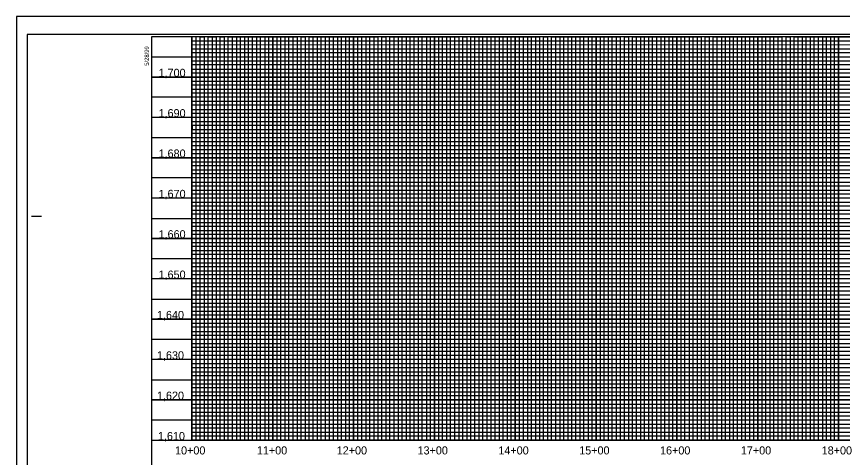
# Model space of a CAD drawing. Extents: x 497599 to 513368, y 404140 to 482942.
# Drawn here: x 505692 to 506714, y 439315 to 439861 of the extents above; entities that cross this region are included whole.
import ezdxf

# ---------------------------------------------------------------- set-up
doc = ezdxf.new("R2010")
doc.units = 0
for name, color, linetype in [('Exist Vertical Profile Vertical Axis Label', 7, 'Continuous'), ('Sheet Cutting Line CELL', 7, 'Continuous'), ('Sheet DOT Grid CELL', 7, 'Continuous'), ('Sheet Layout Profile Border Port 1', 7, 'Continuous'), ('Sheet Plot Border Inside CELL', 7, 'Continuous'), ('Sheet Plot Border Outside CELL', 7, 'Continuous'), ('Sheet Profile CELL', 7, 'Continuous'), ('Sheet Profile Grid Major CELL', 7, 'Continuous'), ('Sheet Profile Grid Middle CELL', 7, 'Continuous'), ('Sheet Profile Grid Minor CELL', 7, 'Continuous')]:
    doc.layers.add(name, color=color, linetype=linetype)

msp = doc.modelspace()

# ---------------------------------------------------------------- linework, layer by layer
at = {"layer": 'Sheet Cutting Line CELL'}
for p, q in [((507375.7, 439861.1), (505691.7, 439861.1)), ((505691.7, 439861.1), (505691.7, 438761.1))]:
    msp.add_line(p, q, dxfattribs=at)
at = {"layer": 'Sheet DOT Grid CELL'}
for p, q in [((505908.7, 439336.1), (505908.7, 439836.1)), ((505958.7, 439336.1), (505958.7, 439836.1)), ((506008.7, 439336.1), (506008.7, 439836.1)), ((506058.7, 439336.1), (506058.7, 439836.1)), ((506108.7, 439336.1), (506108.7, 439836.1)), ((506158.7, 439336.1), (506158.7, 439836.1)), ((506208.7, 439336.1), (506208.7, 439836.1)), ((506258.7, 439336.1), (506258.7, 439836.1)), ((506308.7, 439336.1), (506308.7, 439836.1)), ((506358.7, 439336.1), (506358.7, 439836.1)), ((506408.7, 439336.1), (506408.7, 439836.1)), ((506458.7, 439336.1), (506458.7, 439836.1)), ((506508.7, 439336.1), (506508.7, 439836.1)), ((506558.7, 439336.1), (506558.7, 439836.1)), ((506608.7, 439336.1), (506608.7, 439836.1)), ((506658.7, 439336.1), (506658.7, 439836.1)), ((506708.7, 439336.1), (506708.7, 439836.1)), ((507158.6, 439786.1), (505858.7, 439786.1)), ((507158.6, 439736.1), (505858.7, 439736.1)), ((507158.7, 439686.1), (505858.7, 439686.1)), ((507358.7, 439636.1), (505858.7, 439636.1)), ((507358.7, 439586.1), (505858.7, 439586.1)), ((507358.7, 439536.1), (505858.7, 439536.1)), ((507358.7, 439486.1), (505858.7, 439486.1)), ((507358.7, 439436.1), (505858.7, 439436.1)), ((507358.7, 439386.1), (505858.7, 439386.1))]:
    msp.add_line(p, q, dxfattribs=at)
at = {"layer": 'Sheet Layout Profile Border Port 1'}
msp.add_lwpolyline([(505908.7, 439831.1), (507158.7, 439831.1), (507158.6, 439675.1), (507308.7, 439675.1), (507308.7, 439336.1), (505908.7, 439336.1)], close=True, dxfattribs=at)
at = {"layer": 'Sheet Plot Border Inside CELL'}
msp.add_lwpolyline([(505704.7, 438783.6), (507371.2, 438783.6), (507371.2, 439838.7), (505704.7, 439838.7)], close=True, dxfattribs=at)
at = {"layer": 'Sheet Plot Border Outside CELL'}
msp.add_lwpolyline([(505691.7, 438761.1), (507375.7, 438761.1), (507375.7, 439861.1), (505691.7, 439861.1)], close=True, dxfattribs=at)
at = {"layer": 'Sheet Profile CELL'}
for p, q in [((505710.2, 439613.6), (505722.7, 439613.6)), ((505858.7, 439336.1), (507358.7, 439336.1))]:
    msp.add_line(p, q, dxfattribs=at)
msp.add_lwpolyline([(507358.7, 439836.1), (505858.7, 439836.1), (505858.7, 438786.1), (507358.7, 438786.1)], close=True, dxfattribs=at)
at = {"layer": 'Sheet Profile Grid Major CELL'}
for points in [[(505908.7, 439836.1), (505908.7, 439336.1), (505958.7, 439336.1), (505958.7, 439836.1), (506008.7, 439836.1), (506008.7, 439336.1), (506058.7, 439336.1), (506058.7, 439836.1), (506108.7, 439836.1), (506108.7, 439336.1), (506158.7, 439336.1), (506158.7, 439836.1), (506208.7, 439836.1), (506208.7, 439336.1), (506258.7, 439336.1), (506258.7, 439836.1), (506308.7, 439836.1), (506308.7, 439336.1), (506358.7, 439336.1), (506358.7, 439836.1), (506408.7, 439836.1), (506408.7, 439336.1), (506458.7, 439336.1), (506458.7, 439836.1), (506508.7, 439836.1), (506508.7, 439336.1), (506558.7, 439336.1), (506558.7, 439836.1), (506608.7, 439836.1), (506608.7, 439336.1), (506658.7, 439336.1), (506658.7, 439836.1), (506708.7, 439836.1), (506708.7, 439336.1), (506758.7, 439336.1)], [(505858.7, 439786.1), (507158.7, 439786.1)], [(507158.7, 439736.1), (505858.7, 439736.1), (505858.7, 439686.1), (507158.7, 439686.1)], [(507358.7, 439636.1), (505858.7, 439636.1), (505858.7, 439586.1), (507358.7, 439586.1)], [(507358.7, 439536.1), (505858.7, 439536.1), (505858.7, 439486.1), (507358.7, 439486.1)], [(507358.7, 439436.1), (505858.7, 439436.1), (505858.7, 439436.1), (505858.7, 439386.1), (507358.7, 439386.1)]]:
    msp.add_lwpolyline(points, dxfattribs=at)
at = {"layer": 'Sheet Profile Grid Middle CELL'}
msp.add_line((505858.7, 439811.1), (507158.6, 439811.1), dxfattribs=at)
for points in [[(505933.7, 439836.1), (505933.7, 439336.1), (505983.7, 439336.1), (505983.7, 439836.1), (506033.7, 439836.1), (506033.7, 439336.1), (506083.7, 439336.1), (506083.7, 439836.1), (506133.7, 439836.1), (506133.7, 439336.1), (506183.7, 439336.1), (506183.7, 439836.1), (506233.7, 439836.1), (506233.7, 439336.1), (506283.7, 439336.1), (506283.7, 439836.1), (506333.7, 439836.1), (506333.7, 439336.1), (506383.7, 439336.1), (506383.7, 439836.1), (506433.7, 439836.1), (506433.7, 439336.1), (506483.7, 439336.1), (506483.7, 439336.1), (506483.7, 439836.1), (506533.7, 439836.1), (506533.7, 439336.1), (506583.7, 439336.1), (506583.7, 439836.1), (506633.7, 439836.1), (506633.7, 439336.1), (506683.7, 439336.1), (506683.7, 439836.1), (506733.7, 439836.1)], [(507158.7, 439761.1), (505858.7, 439761.1), (505858.7, 439711.1), (507158.7, 439711.1)], [(507358.7, 439661.1), (505858.7, 439661.1), (505858.7, 439611.1), (507183.7, 439611.1)], [(507358.7, 439561.1), (505858.7, 439561.1), (505858.7, 439511.1), (507358.7, 439511.1)], [(507358.7, 439461.1), (505858.7, 439461.1), (505858.7, 439411.1), (507358.7, 439411.1)], [(507358.7, 439361.1), (505858.7, 439361.1)]]:
    msp.add_lwpolyline(points, dxfattribs=at)
at = {"layer": 'Sheet Profile Grid Minor CELL'}
for p, q in [((505908.7, 439831.1), (507158.7, 439831.1)), ((505908.7, 439826.1), (505908.7, 439826.1)), ((507158.7, 439826.1), (505908.7, 439825.8)), ((505908.7, 439821.1), (507158.7, 439821.1)), ((507158.6, 439701.1), (505908.7, 439701.1)), ((507158.7, 439696.1), (505908.7, 439696.1)), ((507158.7, 439691.1), (505908.7, 439691.1)), ((505908.7, 439681.1), (507158.7, 439681.1)), ((507158.7, 439676.1), (505908.7, 439676.1)), ((505908.7, 439671.1), (507308.7, 439671.1)), ((507308.7, 439651.1), (505908.7, 439651.1)), ((505908.7, 439646.1), (507308.7, 439646.1)), ((507308.7, 439626.1), (505908.7, 439626.1)), ((505908.7, 439621.1), (507308.7, 439621.1)), ((507308.7, 439601.1), (505908.7, 439601.1)), ((505908.7, 439596.1), (507308.7, 439596.1)), ((507308.7, 439591.1), (505908.7, 439591.1)), ((505908.7, 439581.1), (507308.7, 439581.1)), ((507308.7, 439576.1), (505908.7, 439576.1)), ((505908.7, 439571.1), (507308.7, 439571.1)), ((507308.7, 439566.1), (505908.7, 439566.1)), ((505908.7, 439556.1), (507308.7, 439556.1)), ((507308.7, 439551.1), (505908.7, 439551.1)), ((505908.7, 439546.1), (507308.7, 439546.1)), ((507308.7, 439541.1), (505908.7, 439541.1)), ((505908.7, 439531.1), (507308.7, 439531.1)), ((507308.7, 439526.1), (505908.7, 439526.1)), ((505908.7, 439521.1), (507308.7, 439521.1)), ((507308.7, 439516.1), (505908.7, 439516.1)), ((505908.7, 439506.1), (507308.7, 439506.1)), ((507308.7, 439501.1), (505908.7, 439501.1)), ((505908.7, 439496.1), (507308.7, 439496.1)), ((507308.7, 439491.1), (505908.7, 439491.1)), ((505908.7, 439481.1), (507308.7, 439481.1)), ((507308.7, 439476.1), (505908.7, 439476.1)), ((505908.7, 439471.1), (507308.7, 439471.1)), ((507308.7, 439466.1), (505908.7, 439466.1)), ((505908.7, 439456.1), (507308.7, 439456.1)), ((507308.7, 439451.1), (505908.7, 439451.1)), ((507308.7, 439446.1), (505908.7, 439446.1)), ((507308.7, 439441.1), (505908.7, 439441.1)), ((505908.7, 439431.1), (507308.7, 439431.1)), ((507308.7, 439426.1), (505908.7, 439426.1)), ((505908.7, 439421.1), (507308.7, 439421.1)), ((507308.7, 439416.1), (505908.7, 439416.1)), ((505908.7, 439406.1), (507308.7, 439406.1)), ((507308.7, 439401.1), (505908.7, 439401.1)), ((505908.7, 439396.1), (507308.7, 439396.1)), ((507308.7, 439391.1), (505908.7, 439391.1)), ((505908.7, 439381.1), (507308.7, 439381.1)), ((507308.7, 439376.1), (505908.7, 439376.1)), ((505908.7, 439371.1), (507308.7, 439371.1)), ((507308.7, 439366.1), (505908.7, 439366.1)), ((505908.7, 439356.1), (507308.7, 439356.1)), ((507308.7, 439351.1), (505908.7, 439351.1)), ((505908.7, 439346.1), (507308.7, 439346.1))]:
    msp.add_line(p, q, dxfattribs=at)
for points in [[(505913.7, 439836.1), (505913.7, 439336.1), (505918.7, 439336.1), (505918.7, 439836.1), (505923.7, 439836.1), (505923.7, 439336.1), (505928.7, 439336.1), (505928.7, 439836.1), (505938.7, 439836.1), (505938.7, 439336.1), (505943.7, 439336.1), (505943.7, 439836.1), (505948.7, 439836.1), (505948.7, 439336.1), (505953.7, 439336.1), (505963.7, 439336.1), (505968.7, 439336.1), (505968.7, 439836.1), (505973.7, 439836.1), (505973.7, 439336.1), (505978.7, 439336.1), (505978.7, 439836.1), (505988.7, 439836.1), (505988.7, 439336.1), (505993.7, 439336.1), (505993.7, 439836.1), (505998.7, 439836.1), (505998.7, 439336.1), (506003.7, 439336.1), (506003.7, 439836.1), (506013.7, 439836.1), (506013.7, 439336.1), (506018.7, 439336.1), (506018.7, 439836.1), (506023.7, 439836.1), (506023.7, 439336.1), (506028.7, 439336.1), (506028.7, 439836.1), (506038.7, 439836.1), (506038.7, 439336.1), (506043.7, 439336.1), (506043.7, 439836.1), (506048.7, 439836.1), (506048.7, 439336.1), (506053.7, 439336.1), (506053.7, 439836.1), (506063.7, 439836.1), (506063.7, 439336.1), (506068.7, 439336.1), (506068.7, 439836.1), (506073.7, 439836.1), (506073.7, 439336.1), (506078.7, 439336.1), (506078.7, 439836.1), (506088.7, 439836.1), (506088.7, 439336.1), (506093.7, 439336.1), (506093.7, 439836.1), (506098.7, 439836.1), (506098.7, 439336.1), (506103.7, 439336.1), (506103.7, 439836.1), (506113.7, 439836.1), (506113.7, 439336.1), (506118.7, 439336.1), (506118.7, 439836.1), (506123.7, 439836.1), (506123.7, 439336.1)], [(505953.7, 439336.1), (505953.7, 439836.1), (505963.7, 439836.1), (505963.7, 439336.1)], [(506123.7, 439336.1), (506128.7, 439336.1), (506128.7, 439836.1), (506138.7, 439836.1), (506138.7, 439336.1), (506143.7, 439336.1), (506143.7, 439836.1), (506148.7, 439836.1), (506148.7, 439336.1), (506153.7, 439336.1), (506153.7, 439836.1), (506163.7, 439836.1), (506163.7, 439336.1), (506168.7, 439336.1), (506168.7, 439836.1), (506173.7, 439836.1), (506173.7, 439336.1), (506178.7, 439336.1), (506178.7, 439836.1), (506188.7, 439836.1), (506188.7, 439336.1), (506193.7, 439336.1), (506193.7, 439836.1), (506198.7, 439836.1), (506198.7, 439336.1), (506203.7, 439336.1), (506203.7, 439836.1), (506213.7, 439836.1), (506213.7, 439336.1), (506218.7, 439336.1), (506218.7, 439836.1), (506223.7, 439836.1), (506223.7, 439336.1), (506228.7, 439336.1), (506228.7, 439836.1), (506238.7, 439836.1), (506238.7, 439336.1), (506243.7, 439336.1), (506243.7, 439836.1), (506248.7, 439836.1), (506248.7, 439336.1), (506253.7, 439336.1), (506253.7, 439836.1), (506263.7, 439836.1), (506263.7, 439336.1), (506268.7, 439336.1), (506268.7, 439836.1), (506273.7, 439836.1), (506273.7, 439336.1), (506278.7, 439336.1), (506278.7, 439836.1), (506288.7, 439836.1), (506288.7, 439336.1), (506293.7, 439336.1), (506293.7, 439836.1), (506298.7, 439836.1), (506298.7, 439336.1), (506303.7, 439336.1), (506303.7, 439836.1), (506313.7, 439836.1), (506313.7, 439336.1), (506318.7, 439336.1), (506318.7, 439836.1), (506323.7, 439836.1), (506323.7, 439336.1), (506328.7, 439336.1), (506328.7, 439836.1), (506338.7, 439836.1), (506338.7, 439336.1), (506343.7, 439336.1), (506343.7, 439836.1), (506348.7, 439836.1), (506348.7, 439336.1), (506353.7, 439336.1), (506353.7, 439836.1), (506363.7, 439836.1), (506363.7, 439336.1), (506368.7, 439336.1), (506368.7, 439836.1), (506373.7, 439836.1), (506373.7, 439336.1), (506378.7, 439336.1), (506378.7, 439836.1), (506388.7, 439836.1), (506388.7, 439336.1), (506393.7, 439336.1), (506393.7, 439836.1), (506398.7, 439836.1), (506398.7, 439336.1), (506403.7, 439336.1), (506403.7, 439836.1), (506413.7, 439836.1), (506413.7, 439336.1), (506418.7, 439336.1), (506418.7, 439836.1), (506423.7, 439836.1), (506423.7, 439336.1), (506428.7, 439336.1), (506428.7, 439836.1), (506438.7, 439836.1)], [(506438.7, 439836.1), (506438.7, 439336.1), (506443.7, 439336.1), (506443.7, 439836.1), (506448.7, 439836.1), (506448.7, 439336.1), (506453.7, 439336.1), (506453.7, 439836.1), (506463.7, 439836.1), (506463.7, 439336.1), (506468.7, 439336.1), (506468.7, 439836.1), (506473.7, 439836.1), (506473.7, 439336.1), (506478.7, 439336.1), (506478.7, 439836.1), (506488.7, 439836.1), (506488.7, 439336.1), (506493.7, 439336.1), (506493.7, 439836.1), (506498.7, 439836.1), (506498.7, 439336.1), (506503.7, 439336.1), (506503.7, 439836.1), (506513.7, 439836.1), (506513.7, 439336.1), (506518.7, 439336.1), (506518.7, 439836.1), (506523.7, 439836.1), (506523.7, 439336.1), (506528.7, 439336.1), (506528.7, 439836.1), (506538.7, 439836.1), (506538.7, 439336.1), (506543.7, 439336.1), (506543.7, 439836.1), (506548.7, 439836.1), (506548.7, 439336.1), (506553.7, 439336.1), (506553.7, 439836.1), (506563.7, 439836.1), (506563.7, 439336.1), (506563.7, 439336.1), (506568.7, 439336.1), (506568.7, 439836.1), (506573.7, 439836.1), (506573.7, 439336.1), (506578.7, 439336.1), (506578.7, 439836.1), (506588.7, 439836.1), (506588.7, 439336.1), (506593.7, 439336.1), (506593.7, 439836.1), (506598.7, 439836.1), (506598.7, 439336.1), (506603.7, 439336.1), (506603.7, 439836.1), (506613.7, 439836.1), (506613.7, 439336.1), (506618.7, 439336.1), (506618.7, 439836.1), (506623.7, 439836.1), (506623.7, 439336.1), (506628.7, 439336.1), (506628.7, 439836.1), (506638.7, 439836.1), (506638.7, 439336.1), (506643.7, 439336.1), (506643.7, 439836.1), (506648.7, 439836.1), (506648.7, 439336.1), (506653.7, 439336.1), (506653.7, 439836.1), (506663.7, 439836.1), (506663.7, 439336.1), (506668.7, 439336.1), (506668.7, 439836.1), (506673.7, 439836.1), (506673.7, 439336.1), (506678.7, 439336.1), (506678.7, 439836.1), (506688.7, 439836.1), (506688.7, 439336.1), (506693.7, 439336.1), (506693.7, 439836.1), (506698.7, 439836.1), (506698.7, 439336.1), (506703.7, 439336.1), (506703.7, 439836.1), (506713.7, 439836.1)], [(507158.7, 439816.1), (505908.7, 439816.1), (505908.7, 439806.1), (507158.7, 439806.1)], [(507158.6, 439801.1), (505908.7, 439801.1), (505908.7, 439796.1), (507158.7, 439796.1)], [(507158.7, 439791.1), (505908.7, 439791.1), (505908.7, 439781.1), (507158.7, 439781.1)], [(507158.7, 439776.1), (505908.7, 439776.1), (505908.7, 439771.1), (507158.7, 439771.1)], [(507158.7, 439766.1), (505908.7, 439766.1), (505908.7, 439756.1), (507158.7, 439756.1)], [(507158.7, 439751.1), (505908.7, 439751.1), (505908.7, 439746.1), (507158.7, 439746.1)], [(507158.7, 439741.1), (505908.7, 439741.1), (505908.7, 439731.1), (507158.7, 439731.1)], [(507158.7, 439726), (505908.8, 439726), (505908.8, 439721.1), (507158.7, 439721.1)], [(507158.7, 439716.1), (505908.7, 439716.1), (505908.7, 439706.1), (507158.7, 439706.1)], [(507308.7, 439666.1), (505908.7, 439666.1), (505908.7, 439656.1), (507308.7, 439656.1)], [(507308.7, 439641.1), (505908.7, 439641.1), (505908.7, 439631.1), (507308.7, 439631.1)], [(507308.7, 439616.1), (505908.7, 439616.1), (505908.7, 439606.1), (507308.7, 439606.1)], [(507308.7, 439341.1), (505908.7, 439341.1)]]:
    msp.add_lwpolyline(points, dxfattribs=at)

# ---------------------------------------------------------------- texts
at = {"layer": 'Exist Vertical Profile Vertical Axis Label'}
for s, p in [('1,700', (505867.4, 439786.4)), ('1,690', (505867.4, 439736.4)), ('1,680', (505867.4, 439686.4)), ('1,670', (505867.4, 439636.4)), ('1,660', (505867.4, 439586.4)), ('1,650', (505867.4, 439536.4)), ('1,640', (505865.4, 439486.4)), ('1,630', (505865.4, 439436.4)), ('1,620', (505865.4, 439386.4)), ('1,610', (505866.6, 439336.4)), ('10+00', (505887.8, 439318.6)), ('11+00', (505989, 439318.6)), ('12+00', (506087.8, 439318.6)), ('13+00', (506187.8, 439318.6)), ('14+00', (506287.8, 439318.6)), ('15+00', (506387.8, 439318.6)), ('16+00', (506487.8, 439318.6)), ('17+00', (506587.8, 439318.6)), ('18+00', (506687.8, 439318.6))]:
    msp.add_text(s, height=10, dxfattribs=at).set_placement(p)
at = {"layer": 'Sheet Profile CELL'}
msp.add_text('5/28/99', height=5.25, rotation=90, dxfattribs=at).set_placement((505855.4, 439800.1))

doc.saveas('drawing.dxf')
